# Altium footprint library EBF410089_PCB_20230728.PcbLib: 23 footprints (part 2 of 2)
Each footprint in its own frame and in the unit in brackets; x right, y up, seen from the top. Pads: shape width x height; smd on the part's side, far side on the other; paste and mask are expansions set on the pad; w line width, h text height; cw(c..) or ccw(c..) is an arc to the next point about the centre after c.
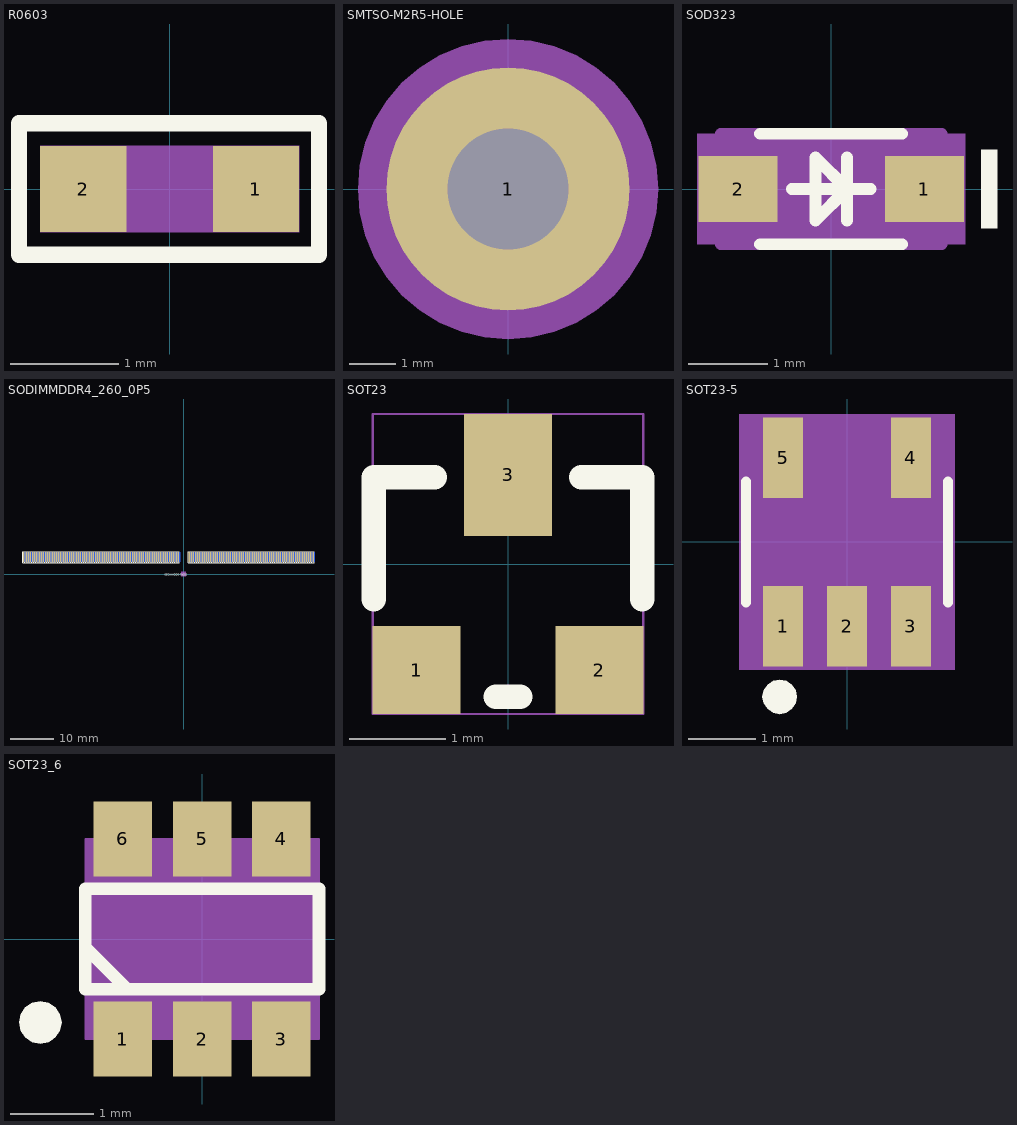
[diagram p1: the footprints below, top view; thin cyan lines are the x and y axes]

## R0603 [mil] "R0603"
pads (2):
  rect 31.5x31.5 smd: 1(31.5,0) 2(-31.5,0)
Top Overlay:
  lines w6: -55,-24 -55,24 54.5,24 54.5,-24 -55,-24
Top 3D Body:
  region: 47.24,15.75 47.24,-15.75 -47.24,-15.75 -47.24,15.75
3D body: height 150, standoff 0, extent -47.24,-15.75 47.24,15.75

## SMTSO-M2R5-HOLE [mm] "SMTSO-M2R5-HOLE"
pads (1):
  round 5.2 / inner round 5.2 / far side round 6.2 hole 2.6: 1(0,0)
Top Overlay:
  text "PTH_M2.5" at -0.421,0.894 h0.15
Top 3D Body:
  region: 3.21,0 3.17,0.502 3.053,0.992 2.86,1.457 2.597,1.887 2.27,2.27 1.887,2.597 1.457,2.86 0.992,3.053 0.502,3.17 0,3.21 -0.502,3.17 -0.992,3.053 -1.457,2.86 -1.601,2.772 -1.887,2.597 -2.27,2.27 -2.597,1.887 -2.86,1.457 -3.053,0.992 -3.17,0.502 -3.21,0 -3.17,-0.502 -3.053,-0.992 -2.86,-1.457 -2.597,-1.887 -2.27,-2.27 -1.887,-2.597 -1.601,-2.772 -1.457,-2.86 -0.992,-3.053 -0.502,-3.17 0,-3.21 0.502,-3.17 0.992,-3.053 1.457,-2.86 1.887,-2.597 2.27,-2.27 2.597,-1.887 2.86,-1.457 3.053,-0.992 3.17,-0.502
Mechanical 12:
  text "1" at -0.254,0 h0.64
Top Assembly:
  dashed: 3.11,0 3.071,0.486 2.957,0.961 2.771,1.412 2.516,1.828 2.199,2.199 1.828,2.516 1.412,2.771 0.961,2.957 0.486,3.071 0,3.11 -0.486,3.071 -0.961,2.957 -1.412,2.771 -1.551,2.686 -1.828,2.516 -2.199,2.199 -2.516,1.828 -2.771,1.412 -2.957,0.961 -3.071,0.486 -3.11,0 -3.071,-0.486 -2.957,-0.961 -2.771,-1.412 -2.516,-1.828 -2.199,-2.199 -1.828,-2.516 -1.551,-2.686 -1.412,-2.771 -0.961,-2.957 -0.486,-3.071 0,-3.11 0.486,-3.071 0.961,-2.957 1.412,-2.771 1.828,-2.516 2.199,-2.199 2.516,-1.828 2.771,-1.412 2.957,-0.961 3.071,-0.486
3D body: height 3.81, standoff 0, extent -3.21,-3.21 3.21,3.21

## SOD323 [mm] "SOD323"
pads (2):
  rect 1x0.83 smd: 1(1.18,0) 2(-1.18,0)
Top Overlay:
  dashed: 1.9,0.5 1.9,-0.5 2.1,-0.5 2.1,0.5
  lines w0.15: -0.9,-0.7 0.9,-0.7 ; -0.9,0.7 0.9,0.7 ; -0.5,0 0.5,0 ; 0.2,-0.4 0.2,0.4 ; -0.2,-0.4 -0.2,0.4 0.2,0 -0.2,-0.4
Top 3D Body:
  region: -1.7,0.7 -1.7,-0.7 1.7,-0.7 1.7,0.7
Mechanical 12:
  text "1" at 1.302,0 h0.3
  text "2" at -1.058,0 h0.3
Top Assembly:
  lines w0.15: -1.4,-0.7 -1.4,0.7 1.4,0.7 1.4,-0.7 -1.4,-0.7
3D body: height 3.81, standoff 0, extent -1.7,-0.7 1.7,0.7

## SODIMMDDR4_260_0P5 [mm] "SODIMMDDR4_260_0P5"
pads (260):
  rect 0.35x2.25 smd: 1(-36.75,3.95) 3(-36.25,3.95) 5(-35.75,3.95) 7(-35.25,3.95) 9(-34.75,3.95) 11(-34.25,3.95) 13(-33.75,3.95) 15(-33.25,3.95) 17(-32.75,3.95) 19(-32.25,3.95) 21(-31.75,3.95) 23(-31.25,3.95) 25(-30.75,3.95) 27(-30.25,3.95) 29(-29.75,3.95) 31(-29.25,3.95) 33(-28.75,3.95) 35(-28.25,3.95) 37(-27.75,3.95) 39(-27.25,3.95) 41(-26.75,3.95) 43(-26.25,3.95) 45(-25.75,3.95) 47(-25.25,3.95) 49(-24.75,3.95) 51(-24.25,3.95) 53(-23.75,3.95) 55(-23.25,3.95) 57(-22.75,3.95) 59(-22.25,3.95) 61(-21.75,3.95) 63(-21.25,3.95) 65(-20.75,3.95) 67(-20.25,3.95) 69(-19.75,3.95) 71(-19.25,3.95) 73(-18.75,3.95) 75(-18.25,3.95) 77(-17.75,3.95) 79(-17.25,3.95) 81(-16.75,3.95) 83(-16.25,3.95) 85(-15.75,3.95) 87(-15.25,3.95) 89(-14.75,3.95) 91(-14.25,3.95) 93(-13.75,3.95) 95(-13.25,3.95) 97(-12.75,3.95) 99(-12.25,3.95) 101(-11.75,3.95) 103(-11.25,3.95) 105(-10.75,3.95) 107(-10.25,3.95) 109(-9.75,3.95) 111(-9.25,3.95) 113(-8.75,3.95) 115(-8.25,3.95) 117(-7.75,3.95) 119(-7.25,3.95) 121(-6.75,3.95) 123(-6.25,3.95) 125(-5.75,3.95) 127(-5.25,3.95) 129(-4.75,3.95) 131(-4.25,3.95) 133(-3.75,3.95) 135(-3.25,3.95) 137(-2.75,3.95) 139(-2.25,3.95) 141(-1.75,3.95) 143(-1.25,3.95) 145(1.25,3.95) 147(1.75,3.95) 149(2.25,3.95) 151(2.75,3.95) 153(3.25,3.95) 155(3.75,3.95) 157(4.25,3.95) 159(4.75,3.95) 161(5.25,3.95) 163(5.75,3.95) 165(6.25,3.95) 167(6.75,3.95) 169(7.25,3.95) 171(7.75,3.95) 173(8.25,3.95) 175(8.75,3.95) 177(9.25,3.95) 179(9.75,3.95) 181(10.25,3.95) 183(10.75,3.95) 185(11.25,3.95) 187(11.75,3.95) 189(12.25,3.95) 191(12.75,3.95) 193(13.25,3.95) 195(13.75,3.95) 197(14.25,3.95) 199(14.75,3.95) 201(15.25,3.95) 203(15.75,3.95) 205(16.25,3.95) 207(16.75,3.95) 209(17.25,3.95) 211(17.75,3.95) 213(18.25,3.95) 215(18.75,3.95) 217(19.25,3.95) 219(19.75,3.95) 221(20.25,3.95) 223(20.75,3.95) 225(21.25,3.95) 227(21.75,3.95) 229(22.25,3.95) 231(22.75,3.95) 233(23.25,3.95) 235(23.75,3.95) 237(24.25,3.95) 239(24.75,3.95) 241(25.25,3.95) 243(25.75,3.95) 245(26.25,3.95) 247(26.75,3.95) 249(27.25,3.95) 251(27.75,3.95) 253(28.25,3.95) 255(28.75,3.95) 257(29.25,3.95) 259(29.75,3.95)
  rect 0.35x2.25 smd far side: 2(-36.5,3.95) 4(-36,3.95) 6(-35.5,3.95) 8(-35,3.95) 10(-34.5,3.95) 12(-34,3.95) 14(-33.5,3.95) 16(-33,3.95) 18(-32.5,3.95) 20(-32,3.95) 22(-31.5,3.95) 24(-31,3.95) 26(-30.5,3.95) 28(-30,3.95) 30(-29.5,3.95) 32(-29,3.95) 34(-28.5,3.95) 36(-28,3.95) 38(-27.5,3.95) 40(-27,3.95) 42(-26.5,3.95) 44(-26,3.95) 46(-25.5,3.95) 48(-25,3.95) 50(-24.5,3.95) 52(-24,3.95) 54(-23.5,3.95) 56(-23,3.95) 58(-22.5,3.95) 60(-22,3.95) 62(-21.5,3.95) 64(-21,3.95) 66(-20.5,3.95) 68(-20,3.95) 70(-19.5,3.95) 72(-19,3.95) 74(-18.5,3.95) 76(-18,3.95) 78(-17.5,3.95) 80(-17,3.95) 82(-16.5,3.95) 84(-16,3.95) 86(-15.5,3.95) 88(-15,3.95) 90(-14.5,3.95) 92(-14,3.95) 94(-13.5,3.95) 96(-13,3.95) 98(-12.5,3.95) 100(-12,3.95) 102(-11.5,3.95) 104(-11,3.95) 106(-10.5,3.95) 108(-10,3.95) 110(-9.5,3.95) 112(-9,3.95) 114(-8.5,3.95) 116(-8,3.95) 118(-7.5,3.95) 120(-7,3.95) 122(-6.5,3.95) 124(-6,3.95) 126(-5.5,3.95) 128(-5,3.95) 130(-4.5,3.95) 132(-4,3.95) 134(-3.5,3.95) 136(-3,3.95) 138(-2.5,3.95) 140(-2,3.95) 142(-1.5,3.95) 144(-1,3.95) 146(1.5,3.95) 148(2,3.95) 150(2.5,3.95) 152(3,3.95) 154(3.5,3.95) 156(4,3.95) 158(4.5,3.95) 160(5,3.95) 162(5.5,3.95) 164(6,3.95) 166(6.5,3.95) 168(7,3.95) 170(7.5,3.95) 172(8,3.95) 174(8.5,3.95) 176(9,3.95) 178(9.5,3.95) 180(10,3.95) 182(10.5,3.95) 184(11,3.95) 186(11.5,3.95) 188(12,3.95) 190(12.5,3.95) 192(13,3.95) 194(13.5,3.95) 196(14,3.95) 198(14.5,3.95) 200(15,3.95) 202(15.5,3.95) 204(16,3.95) 206(16.5,3.95) 208(17,3.95) 210(17.5,3.95) 212(18,3.95) 214(18.5,3.95) 216(19,3.95) 218(19.5,3.95) 220(20,3.95) 222(20.5,3.95) 224(21,3.95) 226(21.5,3.95) 228(22,3.95) 230(22.5,3.95) 232(23,3.95) 234(23.5,3.95) 236(24,3.95) 238(24.5,3.95) 240(25,3.95) 242(25.5,3.95) 244(26,3.95) 246(26.5,3.95) 248(27,3.95) 250(27.5,3.95) 252(28,3.95) 254(28.5,3.95) 256(29,3.95) 258(29.5,3.95) 260(30,3.95)
Top Overlay:
  drawing of 520 lines, arcs and shapes, not listed
  text "DDR4-SODIMM260" at 0.853,0.076 h0.15
Top 3D Body:
  region: 0.5,-0.5 0.5,0.5 -0.5,0.5 -0.5,-0.5
Mechanical 12:
  text "177" at 10.012,3.95 h0.64
  text "230" at 23.262,3.95 h0.64
  text "232" at 23.762,3.95 h0.64
  text "173" at 9.012,3.95 h0.64
  text "154" at 4.262,3.95 h0.64
  text "119" at -6.488,3.95 h0.64
  text "117" at -6.988,3.95 h0.64
  text "115" at -7.488,3.95 h0.64
  text "156" at 4.762,3.95 h0.64
  text "113" at -7.988,3.95 h0.64
  text "158" at 5.262,3.95 h0.64
  text "111" at -8.488,3.95 h0.64
  text "109" at -8.988,3.95 h0.64
  text "107" at -9.488,3.95 h0.64
  text "105" at -9.988,3.95 h0.64
  text "123" at -5.488,3.95 h0.64
  text "121" at -5.988,3.95 h0.64
  text "101" at -10.988,3.95 h0.64
  text "99" at -11.742,3.95 h0.64
  text "97" at -12.242,3.95 h0.64
  text "95" at -12.742,3.95 h0.64
  text "93" at -13.242,3.95 h0.64
  text "91" at -13.742,3.95 h0.64
  text "89" at -14.242,3.95 h0.64
  text "87" at -14.742,3.95 h0.64
  text "194" at 14.262,3.95 h0.64
  text "85" at -15.242,3.95 h0.64
  text "196" at 14.762,3.95 h0.64
  text "83" at -15.742,3.95 h0.64
  text "5" at -35.496,3.95 h0.64
  text "55" at -22.742,3.95 h0.64
  text "81" at -16.242,3.95 h0.64
  text "79" at -16.742,3.95 h0.64
  text "190" at 13.262,3.95 h0.64
  text "192" at 13.762,3.95 h0.64
  text "186" at 12.262,3.95 h0.64
  text "188" at 12.762,3.95 h0.64
  text "233" at 24.012,3.95 h0.64
  text "21" at -31.242,3.95 h0.64
  text "19" at -31.742,3.95 h0.64
  text "118" at -6.738,3.95 h0.64
  text "116" at -7.238,3.95 h0.64
  text "48" at -24.492,3.95 h0.64
  text "112" at -8.238,3.95 h0.64
  text "50" at -23.992,3.95 h0.64
  text "114" at -7.738,3.95 h0.64
  text "42" at -25.992,3.95 h0.64
  text "110" at -8.738,3.95 h0.64
  text "108" at -9.238,3.95 h0.64
  text "106" at -9.738,3.95 h0.64
  text "40" at -26.492,3.95 h0.64
  text "104" at -10.238,3.95 h0.64
  text "122" at -5.738,3.95 h0.64
  text "260" at 30.762,3.95 h0.64
  text "258" at 30.262,3.95 h0.64
  text "259" at 30.512,3.95 h0.64
  text "257" at 30.012,3.95 h0.64
  text "256" at 29.762,3.95 h0.64
  text "255" at 29.512,3.95 h0.64
  text "191" at 13.512,3.95 h0.64
  text "120" at -6.238,3.95 h0.64
  text "189" at 13.012,3.95 h0.64
  text "185" at 12.012,3.95 h0.64
  text "187" at 12.512,3.95 h0.64
  text "54" at -22.992,3.95 h0.64
  text "75" at -17.742,3.95 h0.64
  text "73" at -18.242,3.95 h0.64
  text "71" at -18.742,3.95 h0.64
  text "69" at -19.242,3.95 h0.64
  text "67" at -19.742,3.95 h0.64
  text "65" at -20.242,3.95 h0.64
  text "176" at 9.762,3.95 h0.64
  text "235" at 24.512,3.95 h0.64
  text "152" at 3.762,3.95 h0.64
  text "3" at -35.996,3.95 h0.64
  text "183" at 11.512,3.95 h0.64
  text "181" at 11.012,3.95 h0.64
  text "29" at -29.242,3.95 h0.64
  text "27" at -29.742,3.95 h0.64
  text "68" at -19.492,3.95 h0.64
  text "66" at -19.992,3.95 h0.64
  text "100" at -11.238,3.95 h0.64
  text "64" at -20.492,3.95 h0.64
  text "98" at -11.992,3.95 h0.64
  text "132" at -3.238,3.95 h0.64
  text "17" at -32.242,3.95 h0.64
  text "39" at -26.742,3.95 h0.64
  text "90" at -13.992,3.95 h0.64
  text "92" at -13.492,3.95 h0.64
  text "82" at -15.992,3.95 h0.64
  text "130" at -3.738,3.95 h0.64
  text "128" at -4.238,3.95 h0.64
  text "227" at 22.512,3.95 h0.64
  text "225" at 22.012,3.95 h0.64
  text "223" at 21.512,3.95 h0.64
  text "9" at -34.496,3.95 h0.64
  text "221" at 21.012,3.95 h0.64
  text "7" at -34.996,3.95 h0.64
  text "174" at 9.262,3.95 h0.64
  text "219" at 20.512,3.95 h0.64
  text "172" at 8.762,3.95 h0.64
  text "51" at -23.742,3.95 h0.64
  text "217" at 20.012,3.95 h0.64
  text "170" at 8.262,3.95 h0.64
  text "213" at 19.012,3.95 h0.64
  text "13" at -33.242,3.95 h0.64
  text "168" at 7.762,3.95 h0.64
  text "215" at 19.512,3.95 h0.64
  text "11" at -33.742,3.95 h0.64
  text "44" at -25.492,3.95 h0.64
  text "178" at 10.262,3.95 h0.64
  text "46" at -24.992,3.95 h0.64
  text "246" at 27.262,3.95 h0.64
  text "245" at 27.012,3.95 h0.64
  text "211" at 18.512,3.95 h0.64
  text "209" at 18.012,3.95 h0.64
  text "72" at -18.492,3.95 h0.64
  text "70" at -18.992,3.95 h0.64
  text "62" at -20.992,3.95 h0.64
  text "86" at -14.992,3.95 h0.64
  text "88" at -14.492,3.95 h0.64
  text "84" at -15.492,3.95 h0.64
  text "59" at -21.742,3.95 h0.64
  text "150" at 3.262,3.95 h0.64
  text "148" at 2.762,3.95 h0.64
  text "57" at -22.242,3.95 h0.64
  text "52" at -23.492,3.95 h0.64
  text "78" at -16.992,3.95 h0.64
  text "76" at -17.492,3.95 h0.64
  text "254" at 29.262,3.95 h0.64
  text "252" at 28.762,3.95 h0.64
  text "250" at 28.262,3.95 h0.64
  text "234" at 24.262,3.95 h0.64
  text "228" at 22.762,3.95 h0.64
  text "220" at 20.762,3.95 h0.64
  text "206" at 17.262,3.95 h0.64
  text "198" at 15.262,3.95 h0.64
  text "180" at 10.762,3.95 h0.64
  text "164" at 6.762,3.95 h0.64
  text "146" at 2.262,3.95 h0.64
  text "144" at -0.238,3.95 h0.64
  text "134" at -2.738,3.95 h0.64
  text "124" at -5.238,3.95 h0.64
  text "102" at -10.738,3.95 h0.64
  text "94" at -12.992,3.95 h0.64
  text "80" at -16.492,3.95 h0.64
  text "74" at -17.992,3.95 h0.64
  text "60" at -21.492,3.95 h0.64
  text "56" at -22.492,3.95 h0.64
  text "38" at -26.992,3.95 h0.64
  text "2" at -36.246,3.95 h0.64
  text "253" at 29.012,3.95 h0.64
  text "251" at 28.512,3.95 h0.64
  text "249" at 28.012,3.95 h0.64
  text "237" at 25.012,3.95 h0.64
  text "229" at 23.012,3.95 h0.64
  text "207" at 17.512,3.95 h0.64
  text "193" at 14.012,3.95 h0.64
  text "179" at 10.512,3.95 h0.64
  text "169" at 8.012,3.95 h0.64
  text "157" at 5.012,3.95 h0.64
  text "145" at 2.012,3.95 h0.64
  text "143" at -0.488,3.95 h0.64
  text "125" at -4.988,3.95 h0.64
  text "103" at -10.488,3.95 h0.64
  text "77" at -17.242,3.95 h0.64
  text "63" at -20.742,3.95 h0.64
  text "53" at -23.242,3.95 h0.64
  text "15" at -32.742,3.95 h0.64
  text "1" at -36.496,3.95 h0.64
  text "240" at 25.762,3.95 h0.64
  text "239" at 25.512,3.95 h0.64
  text "58" at -21.992,3.95 h0.64
  text "244" at 26.762,3.95 h0.64
  text "243" at 26.512,3.95 h0.64
  text "242" at 26.262,3.95 h0.64
  text "241" at 26.012,3.95 h0.64
  text "166" at 7.262,3.95 h0.64
  text "236" at 24.762,3.95 h0.64
  text "238" at 25.262,3.95 h0.64
  text "226" at 22.262,3.95 h0.64
  text "222" at 21.262,3.95 h0.64
  text "224" at 21.762,3.95 h0.64
  text "141" at -0.988,3.95 h0.64
  text "139" at -1.488,3.95 h0.64
  text "137" at -1.988,3.95 h0.64
  text "135" at -2.488,3.95 h0.64
  text "133" at -2.988,3.95 h0.64
  text "131" at -3.488,3.95 h0.64
  text "129" at -3.988,3.95 h0.64
  text "153" at 4.012,3.95 h0.64
  text "127" at -4.488,3.95 h0.64
  text "200" at 15.762,3.95 h0.64
  text "126" at -4.738,3.95 h0.64
  text "231" at 23.512,3.95 h0.64
  text "208" at 17.762,3.95 h0.64
  text "218" at 20.262,3.95 h0.64
  text "210" at 18.262,3.95 h0.64
  text "204" at 16.762,3.95 h0.64
  text "212" at 18.762,3.95 h0.64
  text "195" at 14.512,3.95 h0.64
  text "214" at 19.262,3.95 h0.64
  text "197" at 15.012,3.95 h0.64
  text "216" at 19.762,3.95 h0.64
  text "199" at 15.512,3.95 h0.64
  text "201" at 16.012,3.95 h0.64
  text "162" at 6.262,3.95 h0.64
  text "160" at 5.762,3.95 h0.64
  text "205" at 17.012,3.95 h0.64
  text "203" at 16.512,3.95 h0.64
  text "175" at 9.512,3.95 h0.64
  text "159" at 5.512,3.95 h0.64
  text "171" at 8.512,3.95 h0.64
  text "248" at 27.762,3.95 h0.64
  text "247" at 27.512,3.95 h0.64
  text "96" at -12.492,3.95 h0.64
  text "32" at -28.492,3.95 h0.64
  text "61" at -21.242,3.95 h0.64
  text "165" at 7.012,3.95 h0.64
  text "45" at -25.242,3.95 h0.64
  text "30" at -28.992,3.95 h0.64
  text "34" at -27.992,3.95 h0.64
  text "36" at -27.492,3.95 h0.64
  text "142" at -0.738,3.95 h0.64
  text "14" at -32.992,3.95 h0.64
  text "140" at -1.238,3.95 h0.64
  text "138" at -1.738,3.95 h0.64
  text "136" at -2.238,3.95 h0.64
  text "20" at -31.492,3.95 h0.64
  text "18" at -31.992,3.95 h0.64
  text "22" at -30.992,3.95 h0.64
  text "24" at -30.492,3.95 h0.64
  text "28" at -29.492,3.95 h0.64
  text "26" at -29.992,3.95 h0.64
  text "25" at -30.242,3.95 h0.64
  text "23" at -30.742,3.95 h0.64
  text "16" at -32.492,3.95 h0.64
  text "12" at -33.492,3.95 h0.64
  text "10" at -33.992,3.95 h0.64
  text "8" at -34.746,3.95 h0.64
  text "6" at -35.246,3.95 h0.64
  text "202" at 16.262,3.95 h0.64
  text "4" at -35.746,3.95 h0.64
  text "37" at -27.242,3.95 h0.64
  text "35" at -27.742,3.95 h0.64
  text "33" at -28.242,3.95 h0.64
  text "31" at -28.742,3.95 h0.64
  text "147" at 2.512,3.95 h0.64
  text "149" at 3.012,3.95 h0.64
  text "151" at 3.512,3.95 h0.64
  text "155" at 4.512,3.95 h0.64
  text "184" at 11.762,3.95 h0.64
  text "182" at 11.262,3.95 h0.64
  text "43" at -25.742,3.95 h0.64
  text "41" at -26.242,3.95 h0.64
  text "49" at -24.242,3.95 h0.64
  text "167" at 7.512,3.95 h0.64
  text "47" at -24.742,3.95 h0.64
  text "163" at 6.512,3.95 h0.64
  text "161" at 6.012,3.95 h0.64
3D body: height 3.81, standoff 0, extent -0.5,-0.5 0.5,0.5

## SOT23 [mil] "SOT23"
pads (3):
  rect 36x36 smd: 1(-37.5,-43.5) 2(37.5,-43.5)
  rect 36x50 smd: 3(0,36.5)
Top Overlay:
  lines w10: -55,-14.5 -55,35.5 -30,35.5 ; -5,-54.5 5,-54.5 ; 30,35.5 55,35.5 55,-14.5
Top 3D Body:
  lines w1: -55.5,-61.5 55.5,-61.5 55.5,61.5 -55.5,61.5 -55.5,-61.5

## SOT23-5 [mm] "SOT23-5"
pads (5):
  rect 0.599x1.199 smd: 1(-0.95,-1.25) 2(0,-1.25) 3(0.95,-1.25) 4(0.95,1.25) 5(-0.95,1.25)
Top Overlay:
  dashed: -1,-2.045 -1.098,-2.065 -1.18,-2.12 -1.235,-2.202 -1.255,-2.3 -1.235,-2.398 -1.217,-2.425 -1.18,-2.48 -1.098,-2.535 -1,-2.555 -0.902,-2.535 -0.82,-2.48 -0.783,-2.425 -0.765,-2.398 -0.745,-2.3 -0.765,-2.202 -0.82,-2.12 -0.902,-2.065
  lines w0.15: -1.5,-0.9 -1.5,0.9 ; 1.5,-0.9 1.5,0.9
Top 3D Body:
  region: -1.6,1.9 -1.6,-1.9 1.6,-1.9 1.6,1.9
Mechanical 12:
  text "3" at 0.95,-1.29 h0.1
  text "5" at -0.95,1.21 h0.1
  text "1" at -0.95,-1.29 h0.1
  text "2" at 0,-1.29 h0.1
  text "4" at 0.95,1.21 h0.1
Top Assembly:
  lines w0.15: -1.5,-0.85 -1.5,0.85 1.5,0.85 1.5,-0.85 -1.5,-0.85
3D body: height 3.81, standoff 0, extent -1.6,-1.9 1.6,1.9

## SOT23_6 [mm] "SOT23_6"
pads (6):
  rect 0.7x0.9 smd: 1(-0.95,-1.2) 2(0,-1.2) 3(0.95,-1.2) 4(0.95,1.2) 5(0,1.2) 6(-0.95,1.2)
Top Overlay:
  dashed: -2.195,-1 -2.176,-1.098 -2.12,-1.18 -2.038,-1.236 -1.94,-1.255 -1.842,-1.236 -1.815,-1.217 -1.76,-1.18 -1.704,-1.098 -1.685,-1 -1.704,-0.902 -1.76,-0.82 -1.815,-0.783 -1.842,-0.764 -1.94,-0.745 -2.038,-0.764 -2.12,-0.82 -2.176,-0.902
  lines w0.15: -1.4,-0.1 -0.9,-0.6 ; -1.4,-0.6 1.4,-0.6 1.4,0.6 -1.4,0.6 -1.4,-0.6
Top 3D Body:
  region: -1.4,-1.2 1.4,-1.2 1.4,1.2 -1.4,1.2
Mechanical 12:
  text "2" at 0.254,-1.2 h0.64
  text "1" at -0.696,-1.2 h0.64
Top Assembly:
  lines w0.025: -1.4,-1.2 -1.4,1.2 1.4,1.2 1.4,-1.2 -1.4,-1.2
3D body: height 3.81, standoff 0, extent -1.4,-1.2 1.4,1.2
